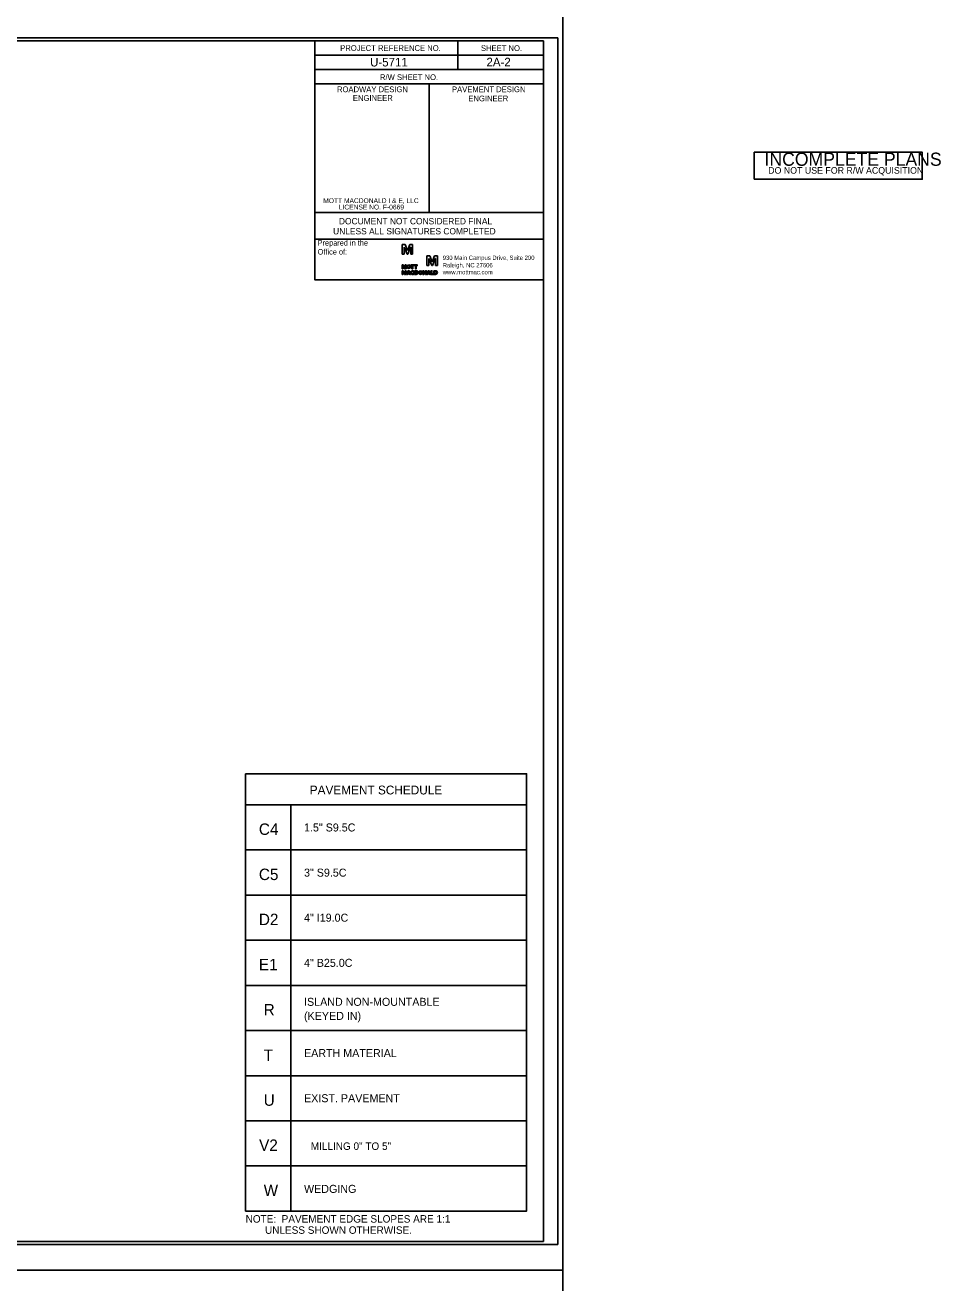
# Model space of a CAD drawing. Extents: x 1901718 to 1902220, y 193828 to 194187.
# Drawn here: x 1902087.2 to 1902167.3, y 193936.9 to 194046.9 of the extents above; entities that cross this region are included whole.
import ezdxf

# ---------------------------------------------------------------- set-up
doc = ezdxf.new("R2010")
doc.units = 0
for name, color, linetype in [('Old_Level_2', 7, 'Continuous'), ('Old_Level_21', 7, 'Continuous'), ('Old_Level_42', 7, 'Continuous'), ('Old_Level_45', 7, 'Continuous'), ('Prop Pavement Schedule Description CELL', 7, 'Continuous'), ('Sheet Border Standard 30in CELL', 7, 'Continuous'), ('Sheet Cutting Line CELL', 7, 'Continuous'), ('Sheet Data Field CELL', 7, 'Continuous'), ('Sheet Plot Border Inside CELL', 7, 'Continuous'), ('Sheet Plot Border Outside CELL', 7, 'Continuous'), ('Sheet Sticker Exception Certification CELL', 7, 'Continuous')]:
    doc.layers.add(name, color=color, linetype=linetype)

msp = doc.modelspace()

# ---------------------------------------------------------------- linework, layer by layer
at = {"layer": 'Old_Level_2'}
for p, q in [((1902120.44, 194027.7), (1902120.18, 194027.7)), ((1902120.18, 194027.7), (1902120.18, 194026.85)), ((1902120.18, 194026.85), (1902120.36, 194026.85)), ((1902120.36, 194026.85), (1902120.36, 194027.46)), ((1902120.36, 194027.46), (1902120.37, 194027.46)), ((1902120.37, 194027.46), (1902120.61, 194026.85)), ((1902120.64, 194027.17), (1902120.44, 194027.7)), ((1902120.61, 194026.85), (1902120.68, 194026.85)), ((1902120.65, 194027.17), (1902120.64, 194027.17)), ((1902120.64, 194027.17), (1902120.64, 194027.17)), ((1902120.85, 194027.7), (1902120.65, 194027.17)), ((1902120.65, 194027.17), (1902120.65, 194027.17)), ((1902120.68, 194026.85), (1902120.92, 194027.46)), ((1902121.1, 194027.7), (1902120.85, 194027.7)), ((1902120.92, 194027.46), (1902120.93, 194027.46)), ((1902120.93, 194027.46), (1902120.93, 194026.85)), ((1902120.93, 194026.85), (1902121.1, 194026.85)), ((1902121.1, 194026.85), (1902121.1, 194027.7)), ((1902120.28, 194025.92), (1902120.18, 194025.92)), ((1902120.18, 194025.92), (1902120.18, 194025.59)), ((1902120.25, 194025.59), (1902120.25, 194025.83)), ((1902120.25, 194025.83), (1902120.25, 194025.83)), ((1902120.25, 194025.83), (1902120.35, 194025.59)), ((1902120.25, 194025.83), (1902120.25, 194025.83)), ((1902120.36, 194025.72), (1902120.28, 194025.92)), ((1902120.44, 194025.92), (1902120.36, 194025.72)), ((1902120.38, 194025.59), (1902120.47, 194025.83)), ((1902120.54, 194025.92), (1902120.44, 194025.92)), ((1902120.47, 194025.83), (1902120.47, 194025.83)), ((1902120.47, 194025.83), (1902120.47, 194025.59)), ((1902120.47, 194025.83), (1902120.47, 194025.83)), ((1902120.47, 194025.83), (1902120.47, 194025.83)), ((1902120.54, 194025.59), (1902120.54, 194025.92)), ((1902120.54, 194025.59), (1902120.54, 194025.92)), ((1902122.6, 194026.71), (1902122.35, 194026.71)), ((1902122.35, 194026.71), (1902122.35, 194025.86)), ((1902122.35, 194025.86), (1902122.53, 194025.86)), ((1902122.53, 194025.86), (1902122.53, 194026.47)), ((1902122.53, 194026.47), (1902122.53, 194026.47)), ((1902122.53, 194026.47), (1902122.77, 194025.86)), ((1902122.8, 194026.18), (1902122.6, 194026.71)), ((1902122.77, 194025.86), (1902122.85, 194025.86)), ((1902122.81, 194026.18), (1902122.8, 194026.18)), ((1902122.8, 194026.18), (1902122.8, 194026.18)), ((1902123.01, 194026.71), (1902122.81, 194026.18)), ((1902122.81, 194026.18), (1902122.81, 194026.18)), ((1902122.85, 194025.86), (1902123.08, 194026.47)), ((1902123.27, 194026.71), (1902123.01, 194026.71)), ((1902123.08, 194026.47), (1902123.09, 194026.47)), ((1902123.09, 194026.47), (1902123.09, 194025.86)), ((1902123.09, 194025.86), (1902123.27, 194025.86)), ((1902123.27, 194025.86), (1902123.27, 194026.71)), ((1902120.18, 194025.59), (1902120.25, 194025.59)), ((1902120.28, 194025.41), (1902120.18, 194025.41)), ((1902120.18, 194025.41), (1902120.18, 194025.09)), ((1902120.18, 194025.09), (1902120.25, 194025.09)), ((1902120.25, 194025.09), (1902120.25, 194025.32)), ((1902120.25, 194025.32), (1902120.25, 194025.32)), ((1902120.25, 194025.32), (1902120.35, 194025.09)), ((1902120.36, 194025.21), (1902120.28, 194025.41)), ((1902120.35, 194025.59), (1902120.38, 194025.59)), ((1902120.35, 194025.09), (1902120.38, 194025.09)), ((1902120.44, 194025.41), (1902120.36, 194025.21)), ((1902120.38, 194025.09), (1902120.47, 194025.32)), ((1902120.54, 194025.41), (1902120.44, 194025.41)), ((1902120.47, 194025.59), (1902120.54, 194025.59)), ((1902120.47, 194025.32), (1902120.47, 194025.32)), ((1902120.47, 194025.32), (1902120.47, 194025.09)), ((1902120.47, 194025.09), (1902120.54, 194025.09)), ((1902120.54, 194025.09), (1902120.54, 194025.41)), ((1902121.22, 194025.16), (1902121.16, 194025.18)), ((1902121.22, 194025.16), (1902121.16, 194025.18)), ((1902121.17, 194025.31), (1902121.23, 194025.33)), ((1902121.17, 194025.31), (1902121.23, 194025.33)), ((1902121.42, 194025.41), (1902121.27, 194025.41)), ((1902121.27, 194025.41), (1902121.27, 194025.25)), ((1902121.27, 194025.25), (1902121.27, 194025.09)), ((1902121.27, 194025.09), (1902121.42, 194025.09)), ((1902121.34, 194025.15), (1902121.34, 194025.35)), ((1902121.34, 194025.35), (1902121.42, 194025.35)), ((1902121.42, 194025.15), (1902121.34, 194025.15)), ((1902122.96, 194025.41), (1902122.96, 194025.41)), ((1902123.1, 194025.41), (1902122.96, 194025.41)), ((1902122.96, 194025.41), (1902122.96, 194025.25)), ((1902122.96, 194025.25), (1902122.96, 194025.09)), ((1902122.96, 194025.09), (1902123.1, 194025.09)), ((1902123.02, 194025.15), (1902123.02, 194025.35)), ((1902123.02, 194025.35), (1902123.1, 194025.35)), ((1902123.1, 194025.15), (1902123.02, 194025.15)), ((1902123.1, 194025.35), (1902123.1, 194025.35))]:
    msp.add_line(p, q, dxfattribs=at)
for points in [[(1902120.95, 194025.86), (1902121.04, 194025.86), (1902121.04, 194025.59), (1902121.11, 194025.59), (1902121.11, 194025.86), (1902121.2, 194025.86), (1902121.2, 194025.92), (1902120.95, 194025.92), (1902120.95, 194025.86)], [(1902121.24, 194025.86), (1902121.34, 194025.86), (1902121.34, 194025.59), (1902121.41, 194025.59), (1902121.41, 194025.86), (1902121.5, 194025.86), (1902121.5, 194025.92), (1902121.24, 194025.92), (1902121.24, 194025.86)], [(1902120.58, 194025.09), (1902120.65, 194025.09), (1902120.68, 194025.14), (1902120.82, 194025.14), (1902120.84, 194025.09), (1902120.91, 194025.09), (1902120.79, 194025.41), (1902120.7, 194025.41), (1902120.58, 194025.09)], [(1902120.69, 194025.2), (1902120.75, 194025.34), (1902120.8, 194025.2), (1902120.69, 194025.2)], [(1902122.07, 194025.3), (1902122.07, 194025.3), (1902122.23, 194025.09), (1902122.29, 194025.09), (1902122.29, 194025.41), (1902122.23, 194025.41), (1902122.23, 194025.21), (1902122.07, 194025.41), (1902122, 194025.41), (1902122, 194025.09), (1902122.07, 194025.09), (1902122.07, 194025.3)], [(1902122.33, 194025.09), (1902122.41, 194025.09), (1902122.43, 194025.14), (1902122.57, 194025.14), (1902122.59, 194025.09), (1902122.67, 194025.09), (1902122.54, 194025.41), (1902122.46, 194025.41), (1902122.33, 194025.09)], [(1902122.45, 194025.2), (1902122.5, 194025.34), (1902122.56, 194025.2), (1902122.45, 194025.2)], [(1902122.92, 194025.09), (1902122.92, 194025.15), (1902122.78, 194025.15), (1902122.78, 194025.41), (1902122.71, 194025.41), (1902122.71, 194025.09), (1902122.92, 194025.09)], [(1902122.92, 194025.09), (1902122.92, 194025.15), (1902122.78, 194025.15), (1902122.78, 194025.41), (1902122.71, 194025.41), (1902122.71, 194025.09), (1902122.92, 194025.09), (1902122.92, 194025.15)]]:
    msp.add_lwpolyline(points, dxfattribs=at)
msp.add_arc((1902123.1, 194025.25), 0.162, 270, 90, dxfattribs=at)
for centre, major_axis, ratio in [((1902120.76, 194025.76), (0, 0.162), 0.993118), ((1902120.76, 194025.76), (0, 0.106), 0.916103), ((1902121.79, 194025.25), (0, 0.162), 0.993118), ((1902121.79, 194025.25), (0, 0.106), 0.916103)]:
    msp.add_ellipse(centre, major_axis=major_axis, ratio=ratio, dxfattribs=at)
for centre, major_axis, ratio, start_param, end_param in [((1902121.09, 194025.25), (0, 0.162), 0.993118, 5.246647, 10.366427), ((1902121.09, 194025.25), (0, 0.162), 0.993118, 5.246647, 10.366427), ((1902121.09, 194025.25), (0, 0.106), 0.916103, 5.276876, 9.424778), ((1902121.09, 194025.25), (0, 0.106), 0.916103, 5.276876, 10.296021), ((1902121.09, 194025.25), (0, 0.106), 0.916103, 3.141593, 4.012835), ((1902121.42, 194025.25), (0, -0.162), 0.930276, 0, 3.141593), ((1902121.42, 194025.25), (0, -0.101), 0.900832, 0, 3.141593), ((1902123.1, 194025.25), (0, -0.101), 0.900832, 0, 3.141593)]:
    msp.add_ellipse(centre, major_axis=major_axis, ratio=ratio, start_param=start_param, end_param=end_param, dxfattribs=at)
at = {"layer": 'Old_Level_42'}
msp.add_lwpolyline([(1902150.98, 194033.42), (1902150.98, 194035.77), (1902165.68, 194035.77), (1902165.68, 194033.42)], close=True, dxfattribs=at)
msp.add_lwpolyline([(1902132.54, 194024.63), (1902112.54, 194024.63), (1902112.54, 194028.16)], dxfattribs=at)
at = {"layer": 'Prop Pavement Schedule Description CELL'}
msp.add_lwpolyline([(1902106.49, 193981.42), (1902131.06, 193981.42), (1902131.06, 193978.69), (1902106.49, 193978.69)], close=True, dxfattribs=at)
for points in [[(1902110.44, 193974.75), (1902106.49, 193974.75), (1902106.49, 193978.69), (1902131.06, 193978.69), (1902131.06, 193974.75), (1902110.44, 193974.75), (1902110.44, 193978.69)], [(1902110.44, 193970.8), (1902106.49, 193970.8), (1902106.49, 193974.75), (1902131.06, 193974.75), (1902131.06, 193970.8), (1902110.44, 193970.8), (1902110.44, 193974.75)], [(1902110.44, 193966.85), (1902106.49, 193966.85), (1902106.49, 193970.8), (1902131.06, 193970.8), (1902131.06, 193966.85), (1902110.44, 193966.85), (1902110.44, 193970.8)], [(1902110.44, 193962.91), (1902106.49, 193962.91), (1902106.49, 193966.85), (1902131.06, 193966.85), (1902131.06, 193962.91), (1902110.44, 193962.91), (1902110.44, 193966.85)], [(1902110.44, 193958.96), (1902106.49, 193958.96), (1902106.49, 193962.91), (1902131.06, 193962.91), (1902131.06, 193958.96), (1902110.44, 193958.96), (1902110.44, 193962.91)], [(1902110.44, 193955.01), (1902106.49, 193955.01), (1902106.49, 193958.96), (1902131.06, 193958.96), (1902131.06, 193955.01), (1902110.44, 193955.01), (1902110.44, 193958.96)], [(1902110.44, 193951.07), (1902106.49, 193951.07), (1902106.49, 193955.01), (1902131.06, 193955.01), (1902131.06, 193951.07), (1902110.44, 193951.07), (1902110.44, 193955.01)], [(1902110.44, 193947.12), (1902106.49, 193947.12), (1902106.49, 193951.07), (1902131.06, 193951.07), (1902131.06, 193947.12), (1902110.44, 193947.12), (1902110.44, 193951.07)], [(1902110.44, 193943.17), (1902106.49, 193943.17), (1902106.49, 193947.12), (1902131.06, 193947.12), (1902131.06, 193943.17), (1902110.44, 193943.17), (1902110.44, 193947.12)]]:
    msp.add_lwpolyline(points, dxfattribs=at)
at = {"layer": 'Sheet Border Standard 30in CELL'}
for p, q in [((1902125.04, 194045.51), (1902125.04, 194043.01)), ((1902112.54, 194044.26), (1902132.54, 194044.26)), ((1902112.54, 194043.01), (1902132.54, 194043.01)), ((1902112.54, 194043.01), (1902112.54, 194041.76)), ((1902112.54, 194043.01), (1902132.54, 194043.01)), ((1902122.54, 194041.76), (1902122.54, 194030.51))]:
    msp.add_line(p, q, dxfattribs=at)
for points in [[(1902132.54, 194045.51), (1901982.54, 194045.51), (1901982.54, 193940.51), (1902132.54, 193940.51)], [(1902112.54, 194045.51), (1902132.54, 194045.51), (1902132.54, 194043.01), (1902112.54, 194043.01)], [(1902112.54, 194041.76), (1902122.54, 194041.76), (1902122.54, 194030.51), (1902112.54, 194030.51)], [(1902122.54, 194041.76), (1902132.54, 194041.76), (1902132.54, 194030.51), (1902122.54, 194030.51)]]:
    msp.add_lwpolyline(points, close=True, dxfattribs=at)
at = {"layer": 'Sheet Cutting Line CELL'}
for p, q in [((1901965.84, 193938.01), (1902134.24, 193938.01)), ((1902134.24, 193938.01), (1901965.84, 193938.01))]:
    msp.add_line(p, q, dxfattribs=at)
at = {"layer": 'Sheet Plot Border Inside CELL'}
msp.add_lwpolyline([(1902133.79, 194045.77), (1901967.14, 194045.77), (1901967.14, 193940.26), (1902133.79, 193940.26)], close=True, dxfattribs=at)
at = {"layer": 'Sheet Plot Border Outside CELL'}
for points in [[(1902134.24, 194048.01), (1901965.84, 194048.01), (1901965.84, 193938.01), (1902134.24, 193938.01)], [(1902134.24, 193938.01), (1901965.84, 193938.01), (1901965.84, 193828.01), (1902134.24, 193828.01)]]:
    msp.add_lwpolyline(points, close=True, dxfattribs=at)
at = {"layer": 'Sheet Sticker Exception Certification CELL'}
for p, q in [((1902112.54, 194028.16), (1902112.54, 194030.51)), ((1902112.54, 194030.51), (1902132.54, 194030.51)), ((1902132.54, 194030.51), (1902132.54, 194028.16)), ((1902132.54, 194028.16), (1902112.54, 194028.16))]:
    msp.add_line(p, q, dxfattribs=at)

# ---------------------------------------------------------------- texts
at = {"layer": 'Old_Level_2'}
for s, height, p in [('Prepared in the ', 0.4819, (1902112.79, 194027.61)), ('Office of:', 0.482, (1902112.79, 194026.83))]:
    msp.add_text(s, height=height, dxfattribs=at).set_placement(p)
for s, p in [('930 Main Campus Drive, Suite 200', (1902123.73, 194026.36)), ('Raleigh, NC 27606', (1902123.73, 194025.71)), ('www.mottmac.com', (1902123.73, 194025.1))]:
    msp.add_text(s, height=0.375, rotation=360, dxfattribs=at).set_placement(p)
at = {"layer": 'Old_Level_21'}
for s, height, p in [('MILLING 0" TO 5"', 0.653, (1902112.19, 193948.52)), ('W', 1, (1902108.07, 193944.49)), ('WEDGING', 0.7, (1902111.6, 193944.76)), ('NOTE:  PAVEMENT EDGE SLOPES ARE 1:1 ', 0.653, (1902106.49, 193942.16)), ('       UNLESS SHOWN OTHERWISE.', 0.653, (1902106.49, 193941.18))]:
    msp.add_text(s, height=height, dxfattribs=at).set_placement(p)
at = {"layer": 'Old_Level_42'}
for s, height, p in [('INCOMPLETE PLANS', 1.152, (1902151.88, 194034.59)), ('DO NOT USE FOR R/W ACQUISITION', 0.576, (1902152.2, 194033.9))]:
    msp.add_text(s, height=height, rotation=360, dxfattribs=at).set_placement(p)
at = {"layer": 'Old_Level_45'}
for s, p in [('MOTT MACDONALD I & E, LLC', (1902113.28, 194031.33)), (' LICENSE NO. F-0669', (1902114.48, 194030.77))]:
    msp.add_text(s, height=0.4219, rotation=360, dxfattribs=at).set_placement(p)
at = {"layer": 'Prop Pavement Schedule Description CELL'}
for s, height, p in [('PAVEMENT SCHEDULE', 0.7718, (1902112.1, 193979.61)), ('C4', 1, (1902107.65, 193976.07)), ('1.5" S9.5C', 0.7, (1902111.6, 193976.37)), ('C5', 1, (1902107.65, 193972.12)), ('3" S9.5C', 0.7, (1902111.6, 193972.42)), ('D2', 1, (1902107.65, 193968.18)), ('4" I19.0C', 0.7, (1902111.6, 193968.48)), ('E1', 1, (1902107.65, 193964.23)), ('4" B25.0C', 0.7, (1902111.6, 193964.53)), ('R', 1, (1902108.07, 193960.28)), ('ISLAND NON-MOUNTABLE ', 0.7, (1902111.6, 193961.12)), ('(KEYED IN)', 0.7, (1902111.6, 193959.89)), ('T ', 1, (1902108.07, 193956.3)), ('EARTH MATERIAL', 0.7, (1902111.6, 193956.64)), ('U ', 1, (1902108.07, 193952.38)), ('EXIST. PAVEMENT', 0.7, (1902111.6, 193952.69)), ('V2', 1, (1902107.67, 193948.43))]:
    msp.add_text(s, height=height, dxfattribs=at).set_placement(p)
at = {"layer": 'Sheet Border Standard 30in CELL'}
for s, p in [('PROJECT REFERENCE NO.', (1902114.76, 194044.64)), ('SHEET NO.', (1902127.07, 194044.63)), ('R/W SHEET NO.', (1902118.24, 194042.09)), ('ROADWAY DESIGN', (1902114.48, 194041.03)), ('PAVEMENT DESIGN', (1902124.54, 194041.03)), ('ENGINEER', (1902115.87, 194040.27)), ('ENGINEER', (1902125.97, 194040.23))]:
    msp.add_text(s, height=0.5, dxfattribs=at).set_placement(p)
at = {"layer": 'Sheet Data Field CELL'}
for s, p in [('U-5711', (1902117.38, 194043.28)), ('2A-2', (1902127.56, 194043.29))]:
    msp.add_text(s, height=0.75, dxfattribs=at).set_placement(p)
at = {"layer": 'Sheet Sticker Exception Certification CELL'}
for s, p in [('UNLESS ALL SIGNATURES COMPLETED', (1902114.14, 194028.59)), ('DOCUMENT NOT CONSIDERED FINAL', (1902114.65, 194029.47))]:
    msp.add_text(s, height=0.55, dxfattribs=at).set_placement(p)

doc.saveas('drawing.dxf')
